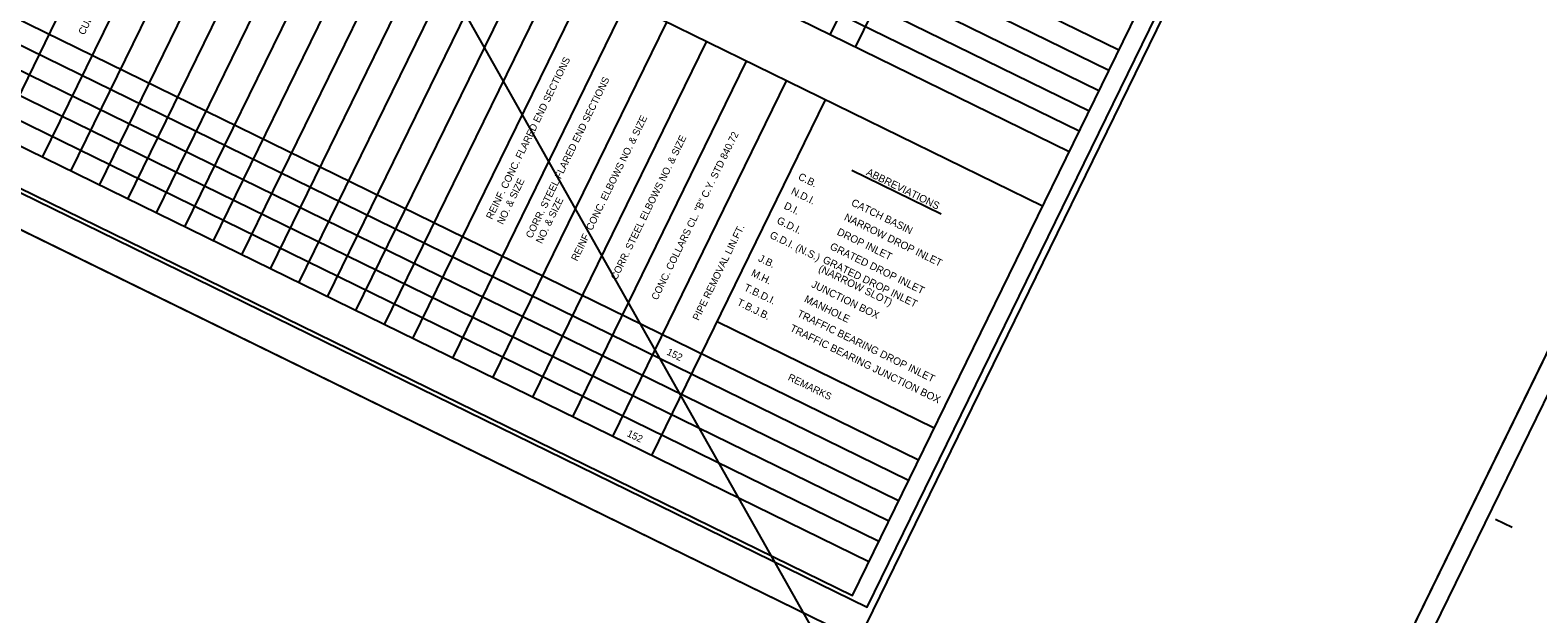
# Model space of a CAD drawing. Extents: x 1523741 to 1527628, y 632733 to 635404.
# Drawn here: x 1524772 to 1525788, y 633628 to 634021 of the extents above; entities that cross this region are included whole.
import ezdxf

# ---------------------------------------------------------------- set-up
doc = ezdxf.new("R2010")
doc.units = 0
for name, color, linetype in [('Scratch_Level_0', 7, 'Continuous'), ('Sheet Cutting Line CELL', 7, 'Continuous'), ('Sheet Pipe Summary CELL', 7, 'Continuous'), ('Sheet Pipe Summary Grid CELL', 7, 'Continuous'), ('Sheet Plot Border Inside CELL', 7, 'Continuous'), ('Sheet Plot Border Outside CELL', 7, 'Continuous'), ('Sheet Summary Combination CELL', 7, 'Continuous'), ('Sheet Summary Combination Grid CELL', 7, 'Continuous')]:
    doc.layers.add(name, color=color, linetype=linetype)

msp = doc.modelspace()

# ---------------------------------------------------------------- linework, layer by layer
at = {"layer": 'Scratch_Level_0'}
msp.add_line((1525401.8, 633436.6), (1524290.2, 635404.2), dxfattribs=at)
at = {"layer": 'Sheet Cutting Line CELL'}
for p, q in [((1526115.7, 634461.2), (1525632.4, 633473.1)), ((1523817.5, 634350.4), (1525330.3, 633610.5))]:
    msp.add_line(p, q, dxfattribs=at)
at = {"layer": 'Sheet Pipe Summary Grid CELL'}
for p, q in [((1525505.7, 634007.8), (1524158.2, 634666.9)), ((1525499, 633994.1), (1524151.5, 634653.2)), ((1525492.3, 633980.4), (1524144.8, 634639.5)), ((1525485.6, 633966.7), (1524138.1, 634625.8)), ((1525478.9, 633953.1), (1524131.4, 634612.1)), ((1525478.9, 633953.1), (1524131.4, 634612.1)), ((1525472.2, 633939.4), (1524124.7, 634598.4)), ((1525472.2, 633939.4), (1524124.7, 634598.4)), ((1525311.1, 634018.2), (1525575.6, 634559.2)), ((1525328.1, 634009.8), (1525592.7, 634550.9)), ((1525328.2, 634009.8), (1525592.7, 634550.9))]:
    msp.add_line(p, q, dxfattribs=at)
at = {"layer": 'Sheet Plot Border Inside CELL'}
for points in [[(1525799.6, 634580.5), (1524302.6, 635312.6), (1523839, 634364.8), (1525336.1, 633632.6)], [(1527614.5, 633703.2), (1526117.5, 634435.3), (1525653.9, 633487.5), (1527151, 632755.4)]]:
    msp.add_lwpolyline(points, close=True, dxfattribs=at)
at = {"layer": 'Sheet Plot Border Outside CELL'}
for points in [[(1525813.5, 634598.6), (1524300.8, 635338.5), (1523817.5, 634350.4), (1525330.3, 633610.5)], [(1527628.4, 633721.4), (1526115.7, 634461.2), (1525632.4, 633473.1), (1527145.1, 632733.2)]]:
    msp.add_lwpolyline(points, close=True, dxfattribs=at)
at = {"layer": 'Sheet Summary Combination CELL'}
for p, q in [((1525385.9, 633897.4), (1525325.7, 633926.8)), ((1525759.6, 633691.9), (1525770.8, 633686.5))]:
    msp.add_line(p, q, dxfattribs=at)
msp.add_lwpolyline([(1525787.3, 634583.7), (1524439.8, 635242.7), (1523978.5, 634299.4), (1525326, 633640.4)], close=True, dxfattribs=at)
at = {"layer": 'Sheet Summary Combination Grid CELL'}
for p, q in [((1525454.3, 633902.8), (1524106.8, 634561.7)), ((1525370.6, 633731.7), (1524023.1, 634390.7)), ((1525363.9, 633718), (1524016.4, 634377)), ((1525357.2, 633704.3), (1524009.7, 634363.3)), ((1525350.5, 633690.6), (1524003, 634349.6)), ((1525343.8, 633676.9), (1523996.3, 634335.9)), ((1525343.8, 633676.9), (1523996.3, 634335.9)), ((1525337.1, 633663.2), (1523989.6, 634322.2)), ((1524750.9, 633949.9), (1524868.1, 634189.5)), ((1524897, 634175.3), (1524779.8, 633935.7)), ((1524799, 633926.3), (1524916.2, 634165.9)), ((1524818.3, 633916.9), (1524935.4, 634156.5)), ((1524837.5, 633907.5), (1524954.6, 634147.1)), ((1524856.7, 633898.1), (1524973.9, 634137.6)), ((1524875.9, 633888.7), (1524993.1, 634128.2)), ((1524895.2, 633879.3), (1525012.3, 634118.8)), ((1524914.4, 633869.9), (1525031.5, 634109.4)), ((1524933.6, 633860.5), (1525050.8, 634100)), ((1524952.8, 633851.1), (1525070, 634090.6)), ((1524972.1, 633841.7), (1525089.2, 634081.2)), ((1524991.3, 633832.3), (1525108.4, 634071.8)), ((1525010.5, 633822.9), (1525127.7, 634062.4)), ((1525029.7, 633813.5), (1525146.9, 634053)), ((1525056.7, 633800.3), (1525173.8, 634039.9)), ((1525083.6, 633787.1), (1525200.8, 634026.7)), ((1525110.6, 633774), (1525227.7, 634013.5)), ((1525137.5, 633760.8), (1525254.7, 634000.3)), ((1525164.5, 633747.6), (1525281.6, 633987.1)), ((1525190.8, 633734.7), (1525308, 633974.4)), ((1525381.1, 633753.2), (1525234.8, 633824.8))]:
    msp.add_line(p, q, dxfattribs=at)

# ---------------------------------------------------------------- texts
at = {"layer": 'Sheet Pipe Summary CELL'}
for s, rotation, p in [('C.B.', 333.9377, (1525289, 633920.9)), ('N.D.I.', 333.9377, (1525284.2, 633911.1)), ('D.I.', 333.9377, (1525279.4, 633901.3)), ('CATCH BASIN', 333.9377, (1525324.8, 633903.4)), ('G.D.I.', 333.9377, (1525274.6, 633891.4)), ('NARROW DROP INLET', 333.9377, (1525320, 633893.6)), ('G.D.I. (N.S.)', 333.9377, (1525269.8, 633881.6)), ('DROP INLET', 333.9377, (1525315.2, 633883.7)), ('GRATED DROP INLET', 333.9377, (1525310.4, 633873.9)), ('J.B.', 333.9377, (1525262.1, 633865.9)), ('GRATED DROP INLET', 333.9651, (1525305.6, 633864.9)), ('M.H.', 333.9377, (1525257.3, 633856)), ('(NARROW SLOT)', 333.9651, (1525302.7, 633859)), ('T.B.D.I.', 333.9377, (1525252.5, 633846.2)), ('JUNCTION BOX', 333.9377, (1525297.9, 633848.4)), ('T.B.J.B.', 333.9377, (1525247.7, 633836.3)), ('TRAFFIC BEARING DROP INLET', 333.9377, (1525288.3, 633828.7)), ('MANHOLE', 333.9377, (1525293.1, 633838.5)), ('TRAFFIC BEARING JUNCTION BOX', 333.9377, (1525283.5, 633818.8))]:
    msp.add_text(s, height=5, rotation=rotation, dxfattribs=at).set_placement(p)
at = {"layer": 'Sheet Summary Combination CELL'}
for s, height, rotation, p in [('CUBIC YARDS', 4.8, 63.9377, (1524808.1, 634017.6)), ('REINF. CONC. FLARED END SECTIONS', 4.8, 63.9377, (1525083, 633893.4)), ('CORR. STEEL FLARED END SECTIONS', 4.8, 63.9609, (1525109.8, 633880.6)), ('REINF. CONC. ELBOWS NO. & SIZE', 4.8, 63.9377, (1525140.4, 633865.3)), ('CORR. STEEL ELBOWS NO. & SIZE', 4.8, 63.9377, (1525167.1, 633852.6)), ('CONC. COLLARS CL. "B" C.Y. STD 840.72', 4.8, 63.9377, (1525194.5, 633839)), ('ABBREVIATIONS', 5, 333.9377, (1525334.9, 633923.9)), ('NO. & SIZE', 4.8, 63.9377, (1525090.4, 633889.9)), ('NO. & SIZE', 4.8, 63.9377, (1525116.6, 633877)), ('PIPE REMOVAL LIN.FT.', 4.8, 63.9377, (1525222.3, 633825.2)), ('152', 4.8, 333.9377, (1525200.4, 633802.9)), ('REMARKS', 4.8, 333.9377, (1525282.1, 633785.8)), ('152', 4.8, 333.9377, (1525173.6, 633748))]:
    msp.add_text(s, height=height, rotation=rotation, dxfattribs=at).set_placement(p)

doc.saveas('drawing.dxf')
